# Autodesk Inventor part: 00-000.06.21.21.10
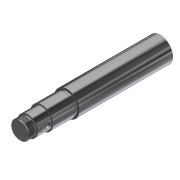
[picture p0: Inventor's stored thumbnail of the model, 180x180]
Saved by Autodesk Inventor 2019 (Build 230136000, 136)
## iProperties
Created: 2019-01
Part Number: 00-000.06.21.21.10
Material: Steel, Mild
Document SubType Name: Modeling
Designer: m.vorobev
Density: 7.85 g/cm^3
Appearance: Semi-Polished
Author: m.vorobev
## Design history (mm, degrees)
sketch "Sketch1"
  geometry: L1 (0, 0)-(18, 0); L2 (18, 0)-(18, -11.5); L3 (18, -11.5)-(0, -11.5); L4 (0, -11.5)-(0, 0); L5 (0, -16)-(20, -16); L6 (20, -16)-(20, -44); L7 (20, -44)-(0, -44); L8 (0, -44)-(0, -16); L9 (0, -44)-(22.5, -44); L10 (22.5, -44)-(22.5, -89); L11 (22.5, -89)-(0, -89); L12 (0, -89)-(0, -44); L13 (0, -89)-(21, -89); L14 (21, -89)-(21, -94); L15 (21, -94)-(0, -94); L16 (0, -94)-(0, -89); L17 (0, -94)-(25, -94); L18 (25, -94)-(25, -280.744); L19 (25, -280.744)-(0, -280.744); L20 (0, -280.744)-(0, -94); L21 (18, -11.5)-(16.8, -12.7); L22 (16.8, -12.7)-(16.8, -16); L23 (0, -11.5)-(0, -16)
  constraints: 46 end point, 10 parallel, 6 perpendicular, 5 horizontal, 2 point on line, 1 collinear
  dimensions: "d0" = 36 diameter of L2 L4; "d1" = 16 distance between parallel lines of L5 L1; "d2" = 4.5 distance between parallel lines of L5 L3; "d3" = 33.6 diameter of L22 L4; "d4" = 45 deg angle of L2 L21; "d5" = 40 diameter of L6 L4; "d6" = 45 diameter of L10 L4; "d7" = 28 distance of L5.end L6.end; "d8" = 94 distance between parallel lines of L1 L17; "d9" = 42 diameter of L14 L4; "d10" = 50 diameter of L18 L4; "d11" = 5 distance of L13.end L14.end
revolve "Revolution1" sketch "Sketch1" stored, may be unused: angle "d12" = 90 deg
fillet "Fillet1" dims "d13" = 0.8
chamfer "Chamfer1" distance "d14" = 1.6; stored, may be unused: second distance "d15" = 2, angle "d16" = 45 deg
workplane "Work Plane1"
sketch "Sketch2"
  geometry: L1 (0, 9)-(0, -11.5); L2 (6, 3)-(6, -5.5); L3 (-6, -5.5)-(-6, 3); L4 (-20, 14)-(20, 14) reference; L5 (-22.5, -14)-(22.5, -14) reference; L6 (-6, 9)-(6, 9); L7 (6, 9)-(6, -11.5); L8 (6, -11.5)-(-6, -11.5); L9 (-6, -11.5)-(-6, 9); L10 (-6, 9)-(6, -11.5); L11 (6, 9)-(-6, -11.5); A1 r 6 centre (0, 3) between (6, 3) and (-6, 3); A2 r 6 centre (0, -5.5) between (-6, -5.5) and (6, -5.5); 3 further points
  constraints: 20 end point, 7 point on circle, 4 midpoint, 4 tangent, 3 parallel, 2 centre point, 2 point on line, 1 collinear, 1 horizontal, 1 perpendicular, 1 vertical, 1 vertical alignment
  dimensions: "d17" = 5 distance from line of L4 L1.start; "d18" = 6 radius of A1; "d19" = 2.5 distance from line of L5 L1.end
extrude "Extrusion1" cut sketch "Sketch2" distance "d20" = 5; taper "d21" = 0 deg
thread "Thread1" dims "d22" = 10, "d23" = 0
body "Solid1"
